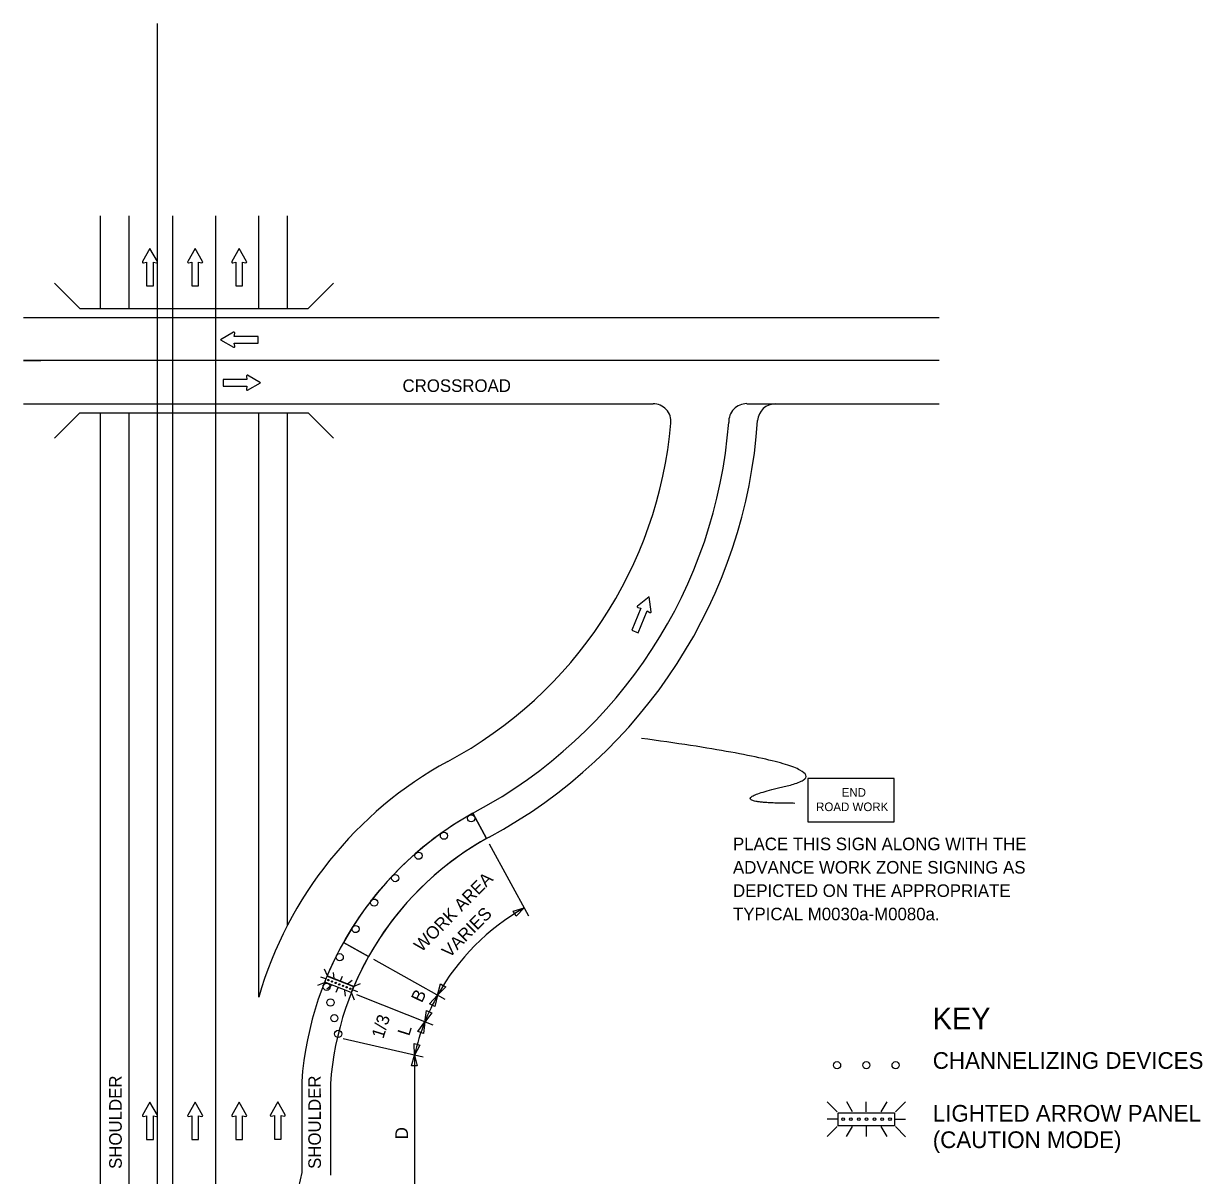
# Model space of a CAD drawing. Extents: x 16480 to 18471, y 4908 to 7082.
# Drawn here: x 16739 to 17395, y 6441 to 7082 of the extents above; entities that cross this region are included whole.
import ezdxf

# ---------------------------------------------------------------- set-up
doc = ezdxf.new("R2010")
doc.units = 0
for name, color, linetype in [('ALI_LEGAL_EX', 7, 'Continuous'), ('MT_SCRATCH_LEVEL_A', 7, 'Continuous'), ('MT_SCRATCH_LEVEL_E', 7, 'Continuous'), ('PAVT_EDGE_EX', 7, 'Continuous'), ('TRAFFIC_SIGNS_PR', 7, 'Continuous'), ('TYPICAL_TEXT_DIMEN_EX', 7, 'Continuous'), ('TYPICAL_TEXT_DIMEN_PR', 7, 'Continuous')]:
    doc.layers.add(name, color=color, linetype=linetype)

msp = doc.modelspace()

# ---------------------------------------------------------------- linework, layer by layer
at = {"layer": 'ALI_LEGAL_EX'}
for p, q in [((16813.1, 6429.87), (16813.1, 7082.19)), ((16821.4, 6975.1), (16821.4, 6020.66)), ((16845.4, 6975.1), (16845.4, 6020.66)), ((17248.19, 6894.57), (16738.55, 6894.57)), ((16893.33, 6442.69), (16893.33, 6442.69))]:
    msp.add_line(p, q, dxfattribs=at)
for points in [[(16821.4, 6975.1), (16821.4, 6950.1)], [(16845.4, 6975.1), (16845.4, 6950.1)], [(16738.55, 6894.57), (16748.19, 6894.57)], [(16738.55, 6894.57), (16748.19, 6894.57)], [(16848.19, 6894.57), (16823.19, 6894.57)], [(16948.19, 6894.57), (16923.19, 6894.57)], [(17048.19, 6894.57), (17023.19, 6894.57)], [(17148.19, 6894.57), (17123.19, 6894.57)], [(17248.19, 6894.57), (17223.19, 6894.57)], [(16821.4, 6865.57), (16821.4, 6850.1)], [(16845.4, 6865.57), (16845.4, 6850.1)], [(16821.4, 6775.1), (16821.4, 6750.1)], [(16845.4, 6775.1), (16845.4, 6750.1)], [(16821.4, 6675.1), (16821.4, 6650.1)], [(16845.4, 6675.1), (16845.4, 6650.1)], [(16821.4, 6575.1), (16821.4, 6550.1)], [(16845.4, 6575.1), (16845.4, 6550.1)], [(16821.4, 6475.1), (16821.4, 6450.1)], [(16845.4, 6475.1), (16845.4, 6450.1)]]:
    msp.add_lwpolyline(points, dxfattribs=at)
at = {"layer": 'MT_SCRATCH_LEVEL_A'}
msp.add_line((17014.38, 6658.19), (17014.43, 6658.27), dxfattribs=at)
at = {"layer": 'MT_SCRATCH_LEVEL_E'}
for p, q in [((16808.89, 6956.98), (16804.78, 6949.74)), ((16813.04, 6949.74), (16808.89, 6956.98)), ((16834.03, 6956.98), (16829.92, 6949.74)), ((16838.18, 6949.74), (16834.03, 6956.98)), ((16858.55, 6956.98), (16854.44, 6949.74)), ((16862.7, 6949.74), (16858.55, 6956.98)), ((16805.26, 6949.06), (16807.04, 6949.37)), ((16807.04, 6949.37), (16807.04, 6936.11)), ((16810.78, 6936.11), (16810.78, 6949.37)), ((16810.78, 6949.37), (16812.56, 6949.06)), ((16830.41, 6949.06), (16832.18, 6949.37)), ((16832.18, 6949.37), (16832.18, 6936.11)), ((16835.92, 6936.11), (16835.92, 6949.37)), ((16835.92, 6949.37), (16837.7, 6949.06)), ((16854.92, 6949.06), (16856.7, 6949.37)), ((16856.7, 6949.37), (16856.7, 6936.11)), ((16860.44, 6936.11), (16860.44, 6949.37)), ((16860.44, 6949.37), (16862.22, 6949.06)), ((16807.04, 6936.11), (16810.78, 6936.11)), ((16832.18, 6936.11), (16835.92, 6936.11)), ((16856.7, 6936.11), (16860.44, 6936.11)), ((16855.42, 6910.34), (16848.18, 6906.19)), ((16855.79, 6908.08), (16856.1, 6909.86)), ((16848.18, 6906.19), (16855.42, 6902.08)), ((16869.05, 6908.08), (16855.79, 6908.08)), ((16856.1, 6902.56), (16855.79, 6904.34)), ((16855.79, 6904.34), (16869.05, 6904.34)), ((16869.05, 6904.34), (16869.05, 6908.08)), ((16862.84, 6884.12), (16849.58, 6884.12)), ((16849.58, 6884.12), (16849.58, 6880.38)), ((16862.53, 6885.89), (16862.84, 6884.12)), ((16870.45, 6882.27), (16863.21, 6886.38)), ((16863.21, 6878.12), (16870.45, 6882.27)), ((16849.58, 6880.38), (16862.84, 6880.38)), ((16862.84, 6880.38), (16862.53, 6878.6)), ((17086.78, 6763.04), (17080.2, 6757.93)), ((17087.83, 6754.77), (17086.78, 6763.04)), ((17082.15, 6756.73), (17077.06, 6744.48)), ((17080.39, 6757.12), (17082.15, 6756.73)), ((17080.52, 6743.05), (17085.6, 6755.29)), ((17085.6, 6755.29), (17087.12, 6754.32)), ((17077.06, 6744.48), (17080.52, 6743.05)), ((16879.99, 6481.95), (16875.88, 6474.71)), ((16884.13, 6474.71), (16879.99, 6481.95)), ((16808.89, 6481.77), (16804.78, 6474.53)), ((16813.04, 6474.53), (16808.89, 6481.77)), ((16834.03, 6481.77), (16829.92, 6474.53)), ((16838.18, 6474.53), (16834.03, 6481.77)), ((16858.55, 6481.77), (16854.44, 6474.53)), ((16862.7, 6474.53), (16858.55, 6481.77)), ((16805.26, 6473.84), (16807.04, 6474.15)), ((16807.04, 6474.15), (16807.04, 6460.9)), ((16810.78, 6460.9), (16810.78, 6474.15)), ((16810.78, 6474.15), (16812.56, 6473.84)), ((16830.41, 6473.84), (16832.18, 6474.15)), ((16832.18, 6474.15), (16832.18, 6460.9)), ((16835.92, 6460.9), (16835.92, 6474.15)), ((16835.92, 6474.15), (16837.7, 6473.84)), ((16854.92, 6473.84), (16856.7, 6474.15)), ((16856.7, 6474.15), (16856.7, 6460.9)), ((16860.44, 6460.9), (16860.44, 6474.15)), ((16860.44, 6474.15), (16862.22, 6473.84)), ((16876.36, 6474.03), (16878.14, 6474.34)), ((16878.14, 6474.34), (16878.14, 6461.08)), ((16881.88, 6461.08), (16881.88, 6474.34)), ((16881.88, 6474.34), (16883.65, 6474.03)), ((16807.04, 6460.9), (16810.78, 6460.9)), ((16832.18, 6460.9), (16835.92, 6460.9)), ((16856.7, 6460.9), (16860.44, 6460.9)), ((16878.14, 6461.08), (16881.88, 6461.08))]:
    msp.add_line(p, q, dxfattribs=at)
for centre, start, end in [((16805.19, 6949.51), 150.42484, 279.96381), ((16812.63, 6949.52), 260.03619, 29.77312), ((16830.33, 6949.51), 150.42484, 279.96381), ((16837.77, 6949.52), 260.03619, 29.77312), ((16854.85, 6949.51), 150.42484, 279.96381), ((16862.29, 6949.52), 260.03619, 29.77312), ((16855.64, 6909.93), 350.03619, 119.77312), ((16855.65, 6902.49), 240.42484, 9.96381), ((16862.98, 6885.97), 60.42484, 189.96381), ((16862.99, 6878.53), 170.03619, 299.77312), ((17080.49, 6757.57), 127.87377, 257.41274), ((17087.37, 6754.72), 237.48513, 7.22205), ((16805.19, 6474.3), 150.42484, 279.96381), ((16812.63, 6474.3), 260.03619, 29.77312), ((16830.33, 6474.3), 150.42484, 279.96381), ((16837.77, 6474.3), 260.03619, 29.77312), ((16854.85, 6474.3), 150.42484, 279.96381), ((16862.29, 6474.3), 260.03619, 29.77312), ((16876.28, 6474.48), 150.42484, 279.96381), ((16883.72, 6474.49), 260.03619, 29.77312)]:
    msp.add_arc(centre, 0.463, start, end, dxfattribs=at)
at = {"layer": 'PAVT_EDGE_EX'}
for p, q in [((16781.4, 6923.57), (16781.4, 6975.1)), ((16797.4, 6923.57), (16797.4, 6975.1)), ((16869.4, 6923.57), (16869.4, 6975.1)), ((16885.4, 6923.57), (16885.4, 6975.1)), ((16769.9, 6923.57), (16755.76, 6937.71)), ((16896.9, 6923.57), (16911.04, 6937.71)), ((16769.9, 6923.57), (16896.9, 6923.57)), ((16738.55, 6918.57), (17248.19, 6918.57)), ((16738.55, 6870.57), (17088.86, 6870.57)), ((17141.02, 6870.57), (17248.19, 6870.57)), ((16755.76, 6851.43), (16769.9, 6865.57)), ((16769.9, 6865.57), (16896.9, 6865.57)), ((16781.4, 6020.66), (16781.4, 6865.57)), ((16797.4, 6020.66), (16797.4, 6865.57)), ((16869.4, 6540.14), (16869.4, 6865.57)), ((16885.4, 6580.25), (16885.4, 6865.57)), ((16911.04, 6851.43), (16896.9, 6865.57)), ((16996.22, 6628.55), (16988.55, 6642.58)), ((16930.5, 6562.79), (16916.54, 6570.59)), ((16916.54, 6570.59), (16930.5, 6562.79)), ((16907.47, 6552), (16922.34, 6546.1)), ((16893.33, 6493.18), (16893.33, 6442.69)), ((16909.29, 6493.18), (16909.29, 6441.07)), ((16893.33, 6442.69), (16869.4, 6333.19))]:
    msp.add_line(p, q, dxfattribs=at)
for centre, radius, start, end in [((17088.86, 6860.57), 10, 355.02362, 90), ((17141.02, 6860.57), 10.03, 90, 182.45519), ((17157.05, 6860.57), 10, 90, 176.17344), ((16862.91, 6880.25), 236.8, 298.14539, 355.02362), ((16862.91, 6880.25), 268.8, 298.20808, 355.71052), ((16862.91, 6880.25), 284.8, 298.23413, 356.17344), ((17079.55, 6479.55), 218.71, 118.67196, 163.91539), ((17079.55, 6479.55), 186.71, 118.67196, 175.81301), ((17079.55, 6479.55), 186.71, 119.16809, 150.81608), ((17079.55, 6479.55), 170.71, 118.67196, 175.81301), ((17079.55, 6479.55), 170.71, 119.21461, 150.81644), ((17079.55, 6479.55), 186.71, 150.81608, 157.16746), ((17079.55, 6479.55), 170.71, 150.81644, 157.05461)]:
    msp.add_arc(centre, radius, start, end, dxfattribs=at)
at = {"layer": 'TRAFFIC_SIGNS_PR'}
for p, q in [((16905.86, 6555.89), (16907.44, 6552.23)), ((16902.28, 6546.88), (16905.94, 6548.45)), ((16906.69, 6550.34), (16904.07, 6551.39)), ((16908.21, 6549.74), (16908.21, 6549.74)), ((16910.23, 6548.93), (16910.23, 6548.93)), ((16911.41, 6550.65), (16910.94, 6553.87)), ((16912.25, 6548.13), (16912.25, 6548.13)), ((16914.95, 6549.24), (16916, 6551.86)), ((16918.8, 6547.71), (16921.35, 6549.73)), ((16922.47, 6546.25), (16926.13, 6547.83)), ((16907.33, 6544.87), (16909.88, 6546.89)), ((16913.45, 6545.47), (16912.41, 6542.85)), ((16914.27, 6547.32), (16914.27, 6547.32)), ((16916.29, 6546.52), (16916.29, 6546.52)), ((16917.79, 6540.7), (16917.32, 6543.93)), ((16918.31, 6545.72), (16918.31, 6545.72)), ((16920.33, 6544.91), (16920.33, 6544.91)), ((16920.96, 6542.48), (16922.54, 6538.81)), ((16921.71, 6544.36), (16924.33, 6543.32)), ((17185.75, 6481.95), (17191.39, 6476.31)), ((17199.93, 6476.31), (17196.67, 6481.95)), ((17207.56, 6476.31), (17207.56, 6481.95)), ((17215.83, 6476.31), (17219.09, 6481.95)), ((17223.73, 6476.31), (17229.37, 6481.96)), ((17191.39, 6472.25), (17185.75, 6472.25)), ((17194.67, 6472.25), (17194.67, 6472.25)), ((17199.02, 6472.25), (17199.02, 6472.25)), ((17203.36, 6472.25), (17203.36, 6472.25)), ((17207.71, 6472.25), (17207.71, 6472.25)), ((17212.06, 6472.25), (17212.06, 6472.25)), ((17216.41, 6472.25), (17216.41, 6472.25)), ((17220.75, 6472.25), (17220.75, 6472.25)), ((17223.73, 6472.25), (17229.37, 6472.25)), ((17185.75, 6462.55), (17191.39, 6468.19)), ((17196.62, 6462.55), (17199.88, 6468.19)), ((17207.56, 6468.19), (17207.56, 6462.55)), ((17219.14, 6462.55), (17215.88, 6468.19)), ((17223.73, 6468.19), (17229.37, 6462.54))]:
    msp.add_line(p, q, dxfattribs=at)
for points in [[(17175.09, 6637.85), (17223.09, 6637.85), (17223.09, 6661.85), (17175.09, 6661.85)], [(16920.83, 6542.78), (16906.24, 6548.58), (16907.57, 6551.93), (16922.17, 6546.12)], [(17223.27, 6468.65), (17191.86, 6468.65), (17191.86, 6475.85), (17223.27, 6475.85)]]:
    msp.add_lwpolyline(points, close=True, dxfattribs=at)
for centre, radius in [((16987.66, 6639.78), 2), ((16972.51, 6630.08), 2), ((16958.37, 6618.95), 2), ((16945.38, 6606.5), 2), ((16933.67, 6592.85), 2), ((16923.33, 6578.12), 2), ((16914.48, 6562.45), 2), ((16907.2, 6546), 2), ((16907.21, 6545.99), 2), ((16908.23, 6549.73), 0.379), ((16910.23, 6548.93), 0.379), ((16912.25, 6548.13), 0.379), ((16914.27, 6547.33), 0.379), ((16916.29, 6546.52), 0.379), ((16918.31, 6545.72), 0.379), ((16920.33, 6544.91), 0.379), ((16909.35, 6537.25), 2), ((16911.5, 6528.51), 2), ((16913.64, 6519.77), 2), ((17191.26, 6502.3), 2), ((17207.56, 6502.3), 2), ((17223.86, 6502.3), 2), ((17194.71, 6472.25), 0.758), ((17199.01, 6472.25), 0.758), ((17203.36, 6472.25), 0.758), ((17207.71, 6472.25), 0.758), ((17212.06, 6472.25), 0.758), ((17216.4, 6472.25), 0.758), ((17220.75, 6472.25), 0.758)]:
    msp.add_circle(centre, radius, dxfattribs=at)
msp.add_open_spline([(17167.83, 6648.11), (17120.6, 6648.11), (17205.62, 6667.46), (17082.52, 6684.25)], degree=2, dxfattribs=at)
at = {"layer": 'TYPICAL_TEXT_DIMEN_PR'}
for p, q in [((16988.55, 6642.58), (16996.22, 6628.55)), ((16997.69, 6625.58), (17019.61, 6585.49)), ((17010.99, 6588.09), (17017.22, 6589.87)), ((17011.86, 6586.65), (17010.99, 6588.09)), ((17017.22, 6589.87), (17012.72, 6585.21)), ((17012.72, 6585.21), (17011.86, 6586.65)), ((16930.5, 6562.79), (16916.54, 6570.59)), ((16973.27, 6538.9), (16933.39, 6561.18)), ((16922.34, 6546.1), (16907.47, 6552)), ((16968.92, 6541.34), (16970.66, 6547.57)), ((16970.66, 6547.57), (16972.1, 6546.72)), ((16922.16, 6546.12), (16922.17, 6546.12)), ((16966.44, 6524.54), (16924.01, 6541.46)), ((16964.53, 6536.58), (16968.92, 6541.34)), ((16968.92, 6541.34), (16967.5, 6535.02)), ((16973.54, 6545.87), (16968.92, 6541.34)), ((16972.1, 6546.72), (16973.54, 6545.87)), ((16966.01, 6535.8), (16964.53, 6536.58)), ((16967.5, 6535.02), (16966.01, 6535.8)), ((16961.81, 6526.38), (16962.72, 6532.78)), ((16965.8, 6531.47), (16961.81, 6526.38)), ((16962.72, 6532.78), (16964.26, 6532.13)), ((16964.26, 6532.13), (16965.8, 6531.47)), ((16957.99, 6521.17), (16961.81, 6526.39)), ((16961.81, 6526.39), (16961.11, 6519.96)), ((16960.9, 6506.76), (16916.39, 6517.06)), ((16959.55, 6520.56), (16957.99, 6521.17)), ((16961.11, 6519.96), (16959.55, 6520.56)), ((16956.04, 6507.88), (16955.87, 6514.35)), ((16955.87, 6514.35), (16957.49, 6513.96)), ((16959.12, 6513.57), (16956.04, 6507.88)), ((16957.49, 6513.96), (16959.12, 6513.57)), ((16954.47, 6502.02), (16956.04, 6507.88)), ((16956.04, 6502.02), (16954.47, 6502.02)), ((16956.04, 6507.88), (16957.61, 6502.02)), ((16956.04, 6507.88), (16956.04, 6417.88)), ((16957.61, 6502.02), (16956.04, 6502.02))]:
    msp.add_line(p, q, dxfattribs=at)
for start, end in [(119.4652, 150.81611), (150.81597, 158.3109), (158.30453, 167.07926)]:
    msp.add_arc((17079.55, 6479.55), 126.71, start, end, dxfattribs=at)

# ---------------------------------------------------------------- texts
at = {"layer": 'TRAFFIC_SIGNS_PR'}
for s, height, p in [('END', 4.789, (17193.85, 6651.77)), ('ROAD WORK', 4.789, (17179.61, 6643.78)), ('PLACE THIS SIGN ALONG WITH THE', 7, (17133.36, 6622.01)), ('ADVANCE WORK ZONE SIGNING AS', 7, (17133.36, 6609.01)), ('DEPICTED ON THE APPROPRIATE', 7, (17133.36, 6596.01)), ('TYPICAL M0030a-M0080a.', 7, (17133.36, 6583.01))]:
    msp.add_text(s, height=height, dxfattribs=at).set_placement(p)
at = {"layer": 'TYPICAL_TEXT_DIMEN_EX'}
for s, height, p in [('KEY', 12, (17244.54, 6522.35)), ('CHANNELIZING DEVICES', 9.3, (17244.54, 6500.3)), ('LIGHTED ARROW PANEL', 9.3, (17244.54, 6470.9)), ('(CAUTION MODE)', 9.3, (17244.54, 6456.2))]:
    msp.add_text(s, height=height, dxfattribs=at).set_placement(p)
at = {"layer": 'TYPICAL_TEXT_DIMEN_PR'}
for s, rotation, p in [('CROSSROAD', 0, (16949.44, 6877.13)), ('WORK AREA', 45.15661, (16960, 6564.97)), ('VARIES', 45.15661, (16975.52, 6561.71)), ('B', 64.56299, (16960.2, 6536.71)), ('1/3', 72.69331, (16938.73, 6516.7)), ('L', 72.69331, (16953.15, 6518.27)), ('SHOULDER', 90.06426, (16793.21, 6444.59)), ('SHOULDER', 90.06426, (16904.03, 6444.59)), ('D', 90, (16952.46, 6461.1))]:
    msp.add_text(s, height=7, rotation=rotation, dxfattribs=at).set_placement(p)

doc.saveas('drawing.dxf')
